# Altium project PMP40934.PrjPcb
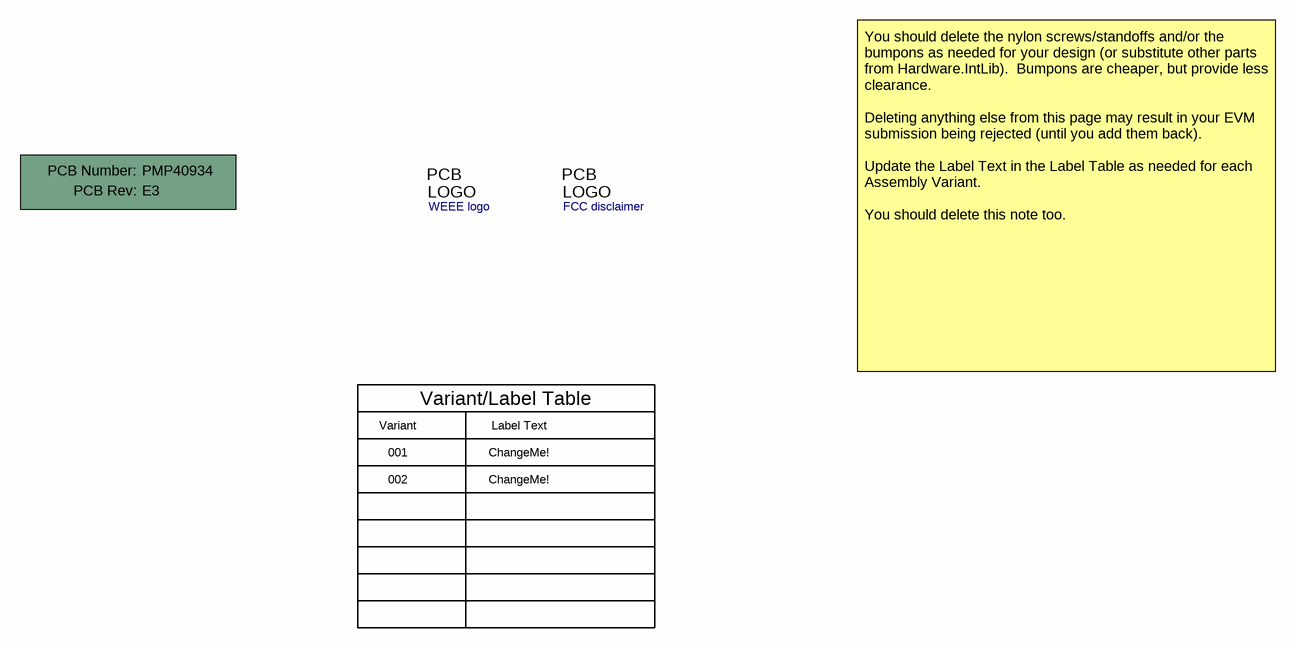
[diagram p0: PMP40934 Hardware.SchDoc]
TID: N/A; TechSupport: http://www.ti.com/support; SCH_Rev: E2; PRJ_Title: Change in menu Project|Project Options|Parameters; PRJ_Number: PMP40934; PRJ_Engineer: Enter name of project lead; PRJ_Customer: Public Release; PCB_Rev: E3; PCB_Layout: Who did the Layout?; CopyrightYear: 2020
3 sheets, 71 parts. Net scope: global (net labels, ports and power ports of the same name join across sheets).
Board file: PMP40934 PCB.PcbDoc
Sheets:
  PMP40934 Hardware.SchDoc
  PMP40934 Input filter.SchDoc
  PMP40934 TPS25762-Q1.SchDoc

## Sheet PMP40934 Hardware.SchDoc
size 431 x 279 mm; Date: Not shown in title block; ApprovedBy: Not shown in title block; CheckedBy: Not shown in title block; Author: Not shown in title block; CompanyName: Not shown in title block; Engineer: Not shown in title block; Organization: Not shown in title block; Address1: Not shown in title block; Address2: Not shown in title block; Address3: Not shown in title block; Address4: Not shown in title block; DocumentNumber: 3; Revision: Use project parameter SCH_Rev; SheetNumber: 3; SheetTotal: 3; PageSetup: Record=PageOptions¦CenterHorizontal=True¦CenterVertical=True¦PrintScale=1.00¦XCorrection=1.00¦YCorrection=1.00¦PrintKind=0¦BorderSize=5000000¦LeftOffset=0¦BottomOffset=0¦Orientation=2¦PaperLength=1000¦PaperWidth=1000¦Scale=100¦PaperSource=15¦PrintQuality=600¦MediaType=1¦DitherType=10¦PaperKind=Letter¦PrintScaleMode=1

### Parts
!PCB1  Printed Circuit Board  (value not drawn)  (mechanical)
Logo1  WEEE logo  [WEEE_Minimum]  (no BOM)
Logo3  FCC disclaimer  [FCC_disclaimer]  (no BOM)

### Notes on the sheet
- Variant
- Variant/Label Table
- Label Text
- You should delete the nylon screws/standoffs and/or the bumpons as needed for your design (or substitute other parts from Hardware.IntLib).  Bumpons are cheaper, but provide less clearance.
  Deleting anything else from this page may result in your EVM submission being rejected (until you add them back).
  Update the Label Text in the Label Table as needed for each Assembly Variant.
  You should delete this note too.
- 001
- 002
- ChangeMe!

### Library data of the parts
!PCB1 = CMP-0003618-2: Manufacturer: Any; PartNumber: PMP40934
Logo1 = CMP-0074769-1
Logo3 = CMP-0074847-1: FCC_disclaimer

## Sheet PMP40934 Input filter.SchDoc
size 431 x 279 mm; Date: Not shown in title block; ApprovedBy: Not shown in title block; CheckedBy: Not shown in title block; Author: Not shown in title block; CompanyName: Not shown in title block; Engineer: Not shown in title block; Organization: Not shown in title block; Address1: Not shown in title block; Address2: Not shown in title block; Address3: Not shown in title block; Address4: Not shown in title block; DocumentNumber: 2; Revision: Use project parameter SCH_Rev; SheetNumber: 2; SheetTotal: 3; PageSetup: Record=PageOptions¦CenterHorizontal=True¦CenterVertical=True¦PrintScale=1.00¦XCorrection=1.00¦YCorrection=1.00¦PrintKind=0¦BorderSize=5000000¦LeftOffset=0¦BottomOffset=0¦Orientation=2¦PaperLength=1000¦PaperWidth=1000¦Scale=100¦PaperSource=15¦PrintQuality=600¦MediaType=1¦DitherType=10¦PaperKind=Letter¦PrintScaleMode=1
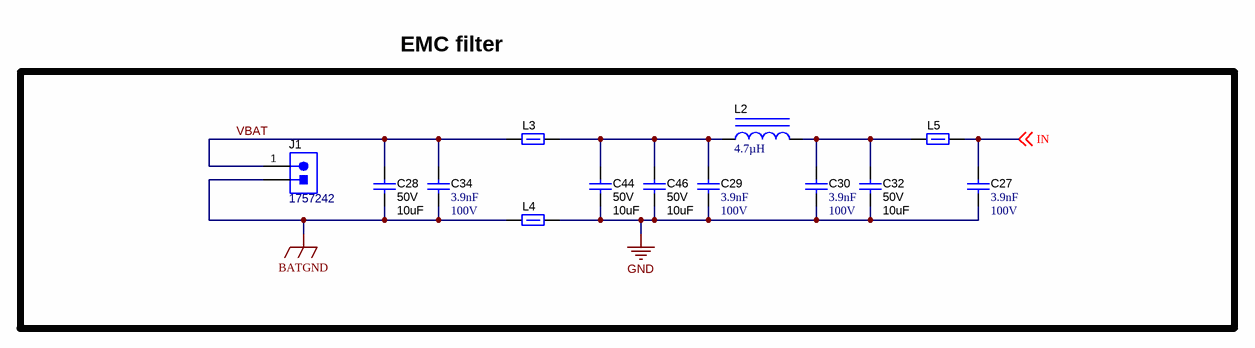
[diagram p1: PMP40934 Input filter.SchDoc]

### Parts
C27  Cap_F: 3.9nF  VDC_V: 100V  [0603]  (hidden comment: GCM1887U2A392JA16D)
C28  VDC_V: 50V  ValueDisplayed: 10uF  [1206_190]  (hidden comment: GRT31CD71H106KE13L)
C29  Cap_F: 3.9nF  VDC_V: 100V  [0603]  (hidden comment: GCM1887U2A392JA16D)
C30  Cap_F: 3.9nF  VDC_V: 100V  [0603]  (hidden comment: GCM1887U2A392JA16D)
C32  VDC_V: 50V  ValueDisplayed: 10uF  [1206_190]  (hidden comment: GRT31CD71H106KE13L)
C34  Cap_F: 3.9nF  VDC_V: 100V  [0603]  (hidden comment: GCM1887U2A392JA16D)
C44  VDC_V: 50V  ValueDisplayed: 10uF  [1206_190]  (hidden comment: GRT31CD71H106KE13L)
C46  VDC_V: 50V  ValueDisplayed: 10uF  [1206_190]  (hidden comment: GRT31CD71H106KE13L)
J1  1757242  [PHOENIX_1757242]
L2  ValueDisplayed: 4.7µH  [XFL5030]  (hidden comment: XFL5030-472MEC)
L3  BLM31SN500SZ1L  [1206]  (value not drawn)
L4  BLM31SN500SZ1L  [1206]  (value not drawn)
L5  BLM31SN500SZ1L  [1206]  (value not drawn)

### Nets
BATGND: C28.2 C34.2 J1.2 L4.1
GND: C27.2 C29.2 C30.2 C32.2 C44.2 C46.2 L4.2  [project net AGND]
IN: C27.1 L5.2 ; off-sheet IN
VBAT: C28.1 C34.1 J1.1 L3.1
NetC29_1: C29.1 C44.1 C46.1 L2.1 L3.2
NetC30_1: C30.1 C32.1 L2.2 L5.1

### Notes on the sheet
- EMC filter

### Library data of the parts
C27 C29 C30 C34 = CMP-0007481-1: CAP, CERM, 3900 pF, 100 V, +/- 10%, X7R, 0603; Manufacturer: MuRata; PartNumber: GRM188R72A392KA01D; TaMin_C: -55°C; Polarized: N; SizeAreaWB_mm2: 4.68; Value1: Unknown; U/M: EA; Value: 3900pF; TaMax_C: 125°C; SizeZ_mm: 1; SizeX_mm: 1.6; SizeY_mm: 0.8; SizeArea_mm2: 1.28; AEC Category: Q200
C28 C32 C44 C46 = CMP-0008808-1: CAP, CERM, 10 µF, 50 V,+/- 10%, X7R, AEC-Q200 Grade 1, 1206; Manufacturer: MuRata; TaMin_C: -55°C; Polarized: N; TempCo: X7T; SizeAreaWB_mm2: 10.92; Value1: Unknown; U/M: EA; Value: 10uF; TaMax_C: 125°C; SizeZ_mm: 1.9; SizeX_mm: 3.2; SizeY_mm: 1.6; Cap_Case: 1206; SizeArea_mm2: 5.12; Cap_F: 10µF; AEC Category: Q200
J1 = CMP-0055534-1: Header (Shrouded), 5.08 mm, 2x1, Tin, R/A, TH; Manufacturer: Phoenix Contact; CT: FALSE
L2 = CMP-0076756-1: Inductor, Shielded, Composite, 4.7 µH, 2.5 A, 0.022 ohm, AEC-Q200 Grade 1, SMD; Manufacturer: Coilcraft; SizeAreaWB_mm2: 54.4544; Irms: 8.7A @ 40C rise; SizeArea_mm2: 28.9344; AEC Qualified: Y; AEC Category: Q200; Value: 4.7uH; SizeZ_mm: 3.1; Imax_A: 2.5A; AEC Grade: 1; SizeY_mm: 5.28; Isat: 2.5A @ 10% inductance drop; DCR_ohm: 0.022; SizeX_mm: 5.48
L3-L5 = CMP-0003367-1: Ferrite Bead, 50 ohm @ 100 MHz, 12 A, 1206; Manufacturer: MuRata; ZTyp@100MHz_Ohm: 50; SizeAreaWB_mm2: 10.92; DCR_ohm: 1.6m; Value1: 0.0016 ohm; Value: 50 ohm; Imax_A: 12A; SizeZ_mm: 1.35; SizeX_mm: 3.2; SizeY_mm: 1.6; SizeArea_mm2: 5.12

## Sheet PMP40934 TPS25762-Q1.SchDoc
size 431 x 279 mm; Date: Not shown in title block; ApprovedBy: Not shown in title block; CheckedBy: Not shown in title block; Author: Not shown in title block; CompanyName: Not shown in title block; Engineer: Not shown in title block; Organization: Not shown in title block; Address1: Not shown in title block; Address2: Not shown in title block; Address3: Not shown in title block; Address4: Not shown in title block; DocumentNumber: 2; Revision: Use project parameter SCH_Rev; SheetNumber: 2; SheetTotal: 3; PageSetup: Record=PageOptions¦CenterHorizontal=True¦CenterVertical=True¦PrintScale=1.00¦XCorrection=1.00¦YCorrection=1.00¦PrintKind=0¦BorderSize=5000000¦LeftOffset=0¦BottomOffset=0¦Orientation=2¦PaperLength=1000¦PaperWidth=1000¦Scale=100¦PaperSource=15¦PrintQuality=600¦MediaType=1¦DitherType=10¦PaperKind=Letter¦PrintScaleMode=1
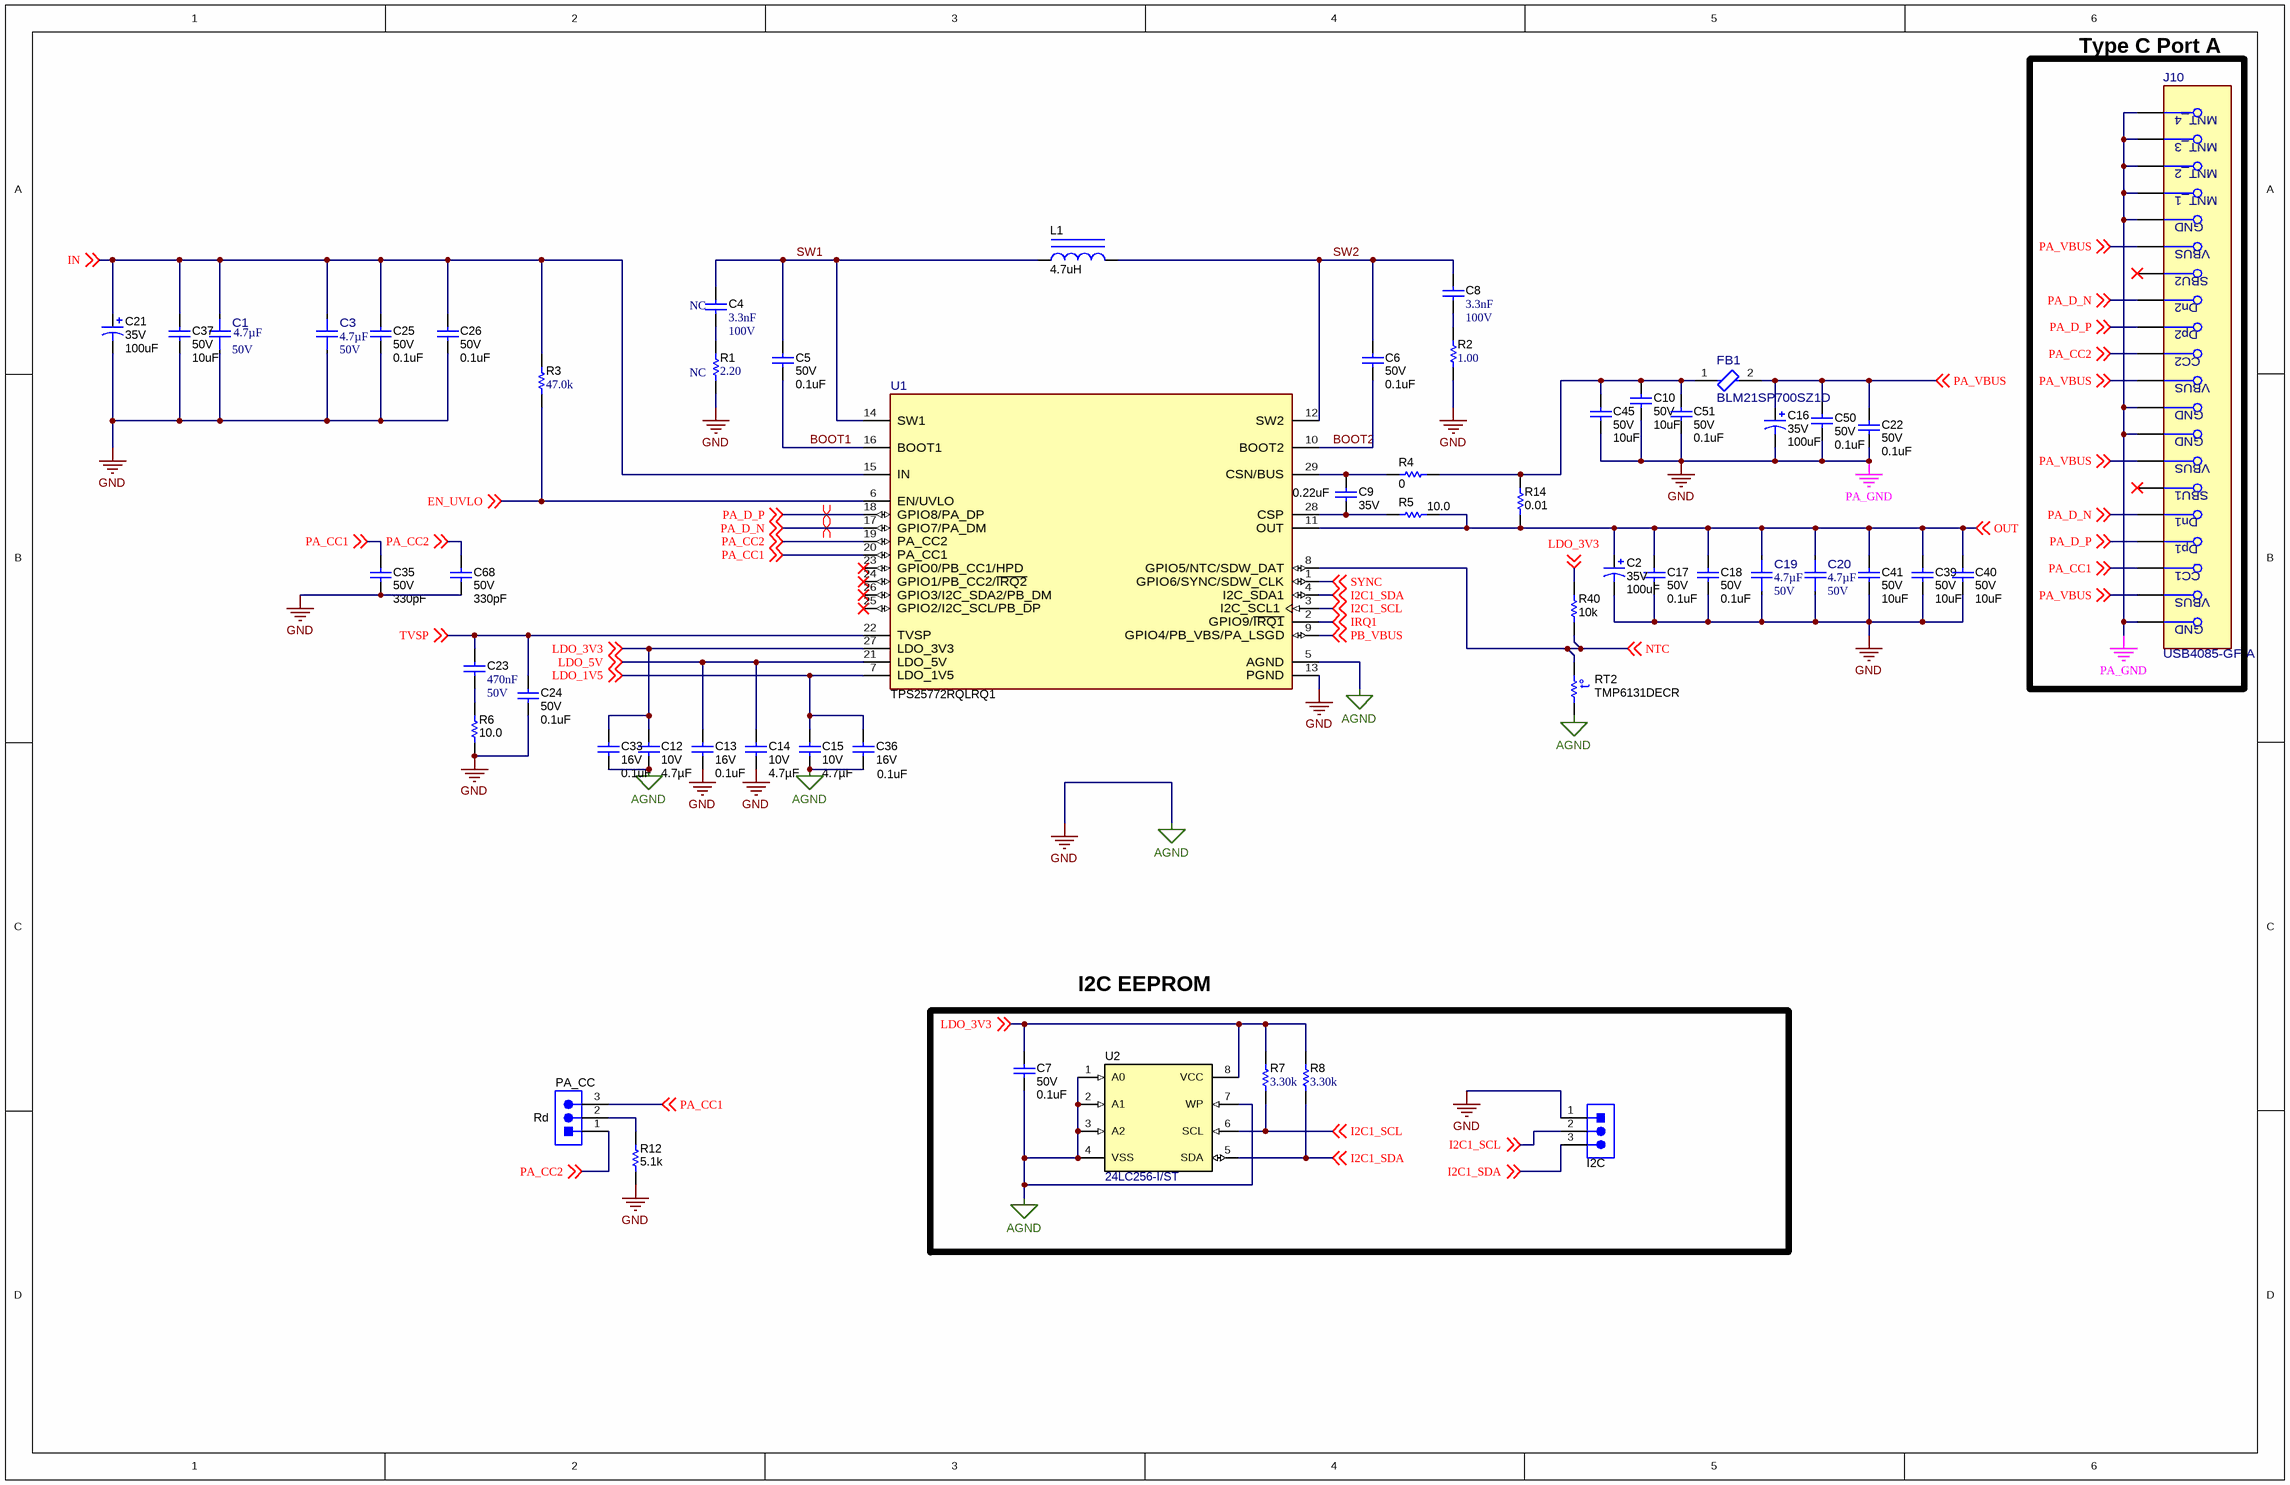
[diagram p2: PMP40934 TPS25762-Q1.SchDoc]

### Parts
C1  Cap_F: 4.7µF  VDC_V: 50V  [FP-CGA4J1X7R1H475K125AC_0805-MFG]  (hidden comment: GRT21BC71H475KE13L)
C2  VDC_V: 35V  ValueDisplayed: 100uF  [Panasonic_D]  (hidden comment: EEHZK1V101XP)
C3  Cap_F: 4.7µF  VDC_V: 50V  [FP-CGA4J1X7R1H475K125AC_0805-MFG]  (hidden comment: GRT21BC71H475KE13L)
C4  Cap_F: 3.3nF  VDC_V: 100V  [0603]  (hidden comment: GRM188R72A332KA01D)
C5  VDC_V: 50V  ValueDisplayed: 0.1uF  [0402L]  (hidden comment: GRT155R71H104KE01D)
C6  VDC_V: 50V  ValueDisplayed: 0.1uF  [0402L]  (hidden comment: GRT155R71H104KE01D)
C7  VDC_V: 50V  ValueDisplayed: 0.1uF  [0402L]  (hidden comment: GRT155R71H104KE01D)
C8  Cap_F: 3.3nF  VDC_V: 100V  [0603]  (hidden comment: GRM188R72A332KA01D)
C9  VDC_V: 35V  ValueDisplayed: 0.22uF  [0402L]  (hidden comment: CGA3E2X7R1H104K080AA)
C10  VDC_V: 50V  ValueDisplayed: 10uF  [1206_190]  (hidden comment: GRT31CD71H106KE13L)
C12  VDC_V: 10V  Cap_F: 4.7µF  [0805L]  (hidden comment: GCM21BR71C475KA73K)
C13  VDC_V: 16V  ValueDisplayed: 0.1uF  [0402L]  (hidden comment: GRT155R71H104KE01D)
C14  VDC_V: 10V  Cap_F: 4.7µF  [0805L]  (hidden comment: GCM21BR71C475KA73K)
C15  VDC_V: 10V  Cap_F: 4.7µF  [0805L]  (hidden comment: GCM21BR71C475KA73K)
C16  VDC_V: 35V  ValueDisplayed: 100uF  [Panasonic_D]  (hidden comment: EEHZK1V101XP)
C17  VDC_V: 50V  ValueDisplayed: 0.1uF  [0402L]  (hidden comment: GRT155R71H104KE01D)
C18  VDC_V: 50V  ValueDisplayed: 0.1uF  [0402L]  (hidden comment: GRT155R71H104KE01D)
C19  Cap_F: 4.7µF  VDC_V: 50V  [FP-CGA4J1X7R1H475K125AC_0805-MFG]  (hidden comment: GRT21BC71H475KE13L)
C20  Cap_F: 4.7µF  VDC_V: 50V  [FP-CGA4J1X7R1H475K125AC_0805-MFG]  (hidden comment: GRT21BC71H475KE13L)
C21  VDC_V: 35V  ValueDisplayed: 100uF  [Panasonic_D]  (hidden comment: EEHZK1V101XP)
C22  VDC_V: 50V  ValueDisplayed: 0.1uF  [0402L]  (hidden comment: GRT155R71H104KE01D)
C23  Cap_F: 470nF  VDC_V: 50V  [0603]  (hidden comment: CGA3E3X7R1H474K080AE)
C24  VDC_V: 50V  ValueDisplayed: 0.1uF  [0402L]  (hidden comment: GRT155R71H104KE01D)
C25  VDC_V: 50V  ValueDisplayed: 0.1uF  [0402L]  (hidden comment: GRT155R71H104KE01D)
C26  VDC_V: 50V  ValueDisplayed: 0.1uF  [0402L]  (hidden comment: GRT155R71H104KE01D)
C33  VDC_V: 16V  ValueDisplayed: 0.1uF  [0402L]  (hidden comment: GRT155R71H104KE01D)
C35  VDC_V: 50V  ValueDisplayed: 330pF  [0402]  (hidden comment: GRM155R71H331KA01D)
C36  VDC_V: 16V  ValueDisplayed: 0.1uF  [0402L]  (hidden comment: GRT155R71H104KE01D)
C37  VDC_V: 50V  ValueDisplayed: 10uF  [1206_190]  (hidden comment: GRT31CD71H106KE13L)
C39  VDC_V: 50V  ValueDisplayed: 10uF  [1206_190]  (hidden comment: GRT31CD71H106KE13L)
C40  VDC_V: 50V  ValueDisplayed: 10uF  [1206_190]  (hidden comment: GRT31CD71H106KE13L)
C41  VDC_V: 50V  ValueDisplayed: 10uF  [1206_190]  (hidden comment: GRT31CD71H106KE13L)
C45  VDC_V: 50V  ValueDisplayed: 10uF  [1206_190]  (hidden comment: GRT31CD71H106KE13L)
C50  VDC_V: 50V  ValueDisplayed: 0.1uF  [0402L]  (hidden comment: GRT155R71H104KE01D)
C51  VDC_V: 50V  ValueDisplayed: 0.1uF  [0402L]  (hidden comment: GRT155R71H104KE01D)
C68  VDC_V: 50V  ValueDisplayed: 330pF  [0402]  (hidden comment: GRM155R71H331KA01D)
FB1  BLM21SP700SZ1D  [0805_HV1]
I2C  61300311121  [WURTH_61300311121]  (value not drawn)
J10  USB4085-GF-A  [FP-USB4085-GF-A_PTH_USB-C-MFG]
L1  ValueDisplayed: 4.7uH  [XAL1010]  (hidden comment: XAL1010-472MEB)
PA_CC  61300311121  [WURTH_61300311121]  (value not drawn)
R1  ValueDisplayed: 2.20  [1206]  (hidden comment: ERJ-8RQF2R2V)
R2  ValueDisplayed: 1.00  [1206]  (hidden comment: CRCW12061R00FKEA)
R3  ValueDisplayed: 47.0k  [0603]  (hidden comment: CRCW060347K0FKEA)
R4  ValueDisplayed: 0  [0402L]  (hidden comment: RMCF0603ZT0R00)
R5  ValueDisplayed: 10.0  [0402L]  (hidden comment: RMCF0603ZT0R00)
R6  ValueDisplayed: 10.0  [1206L]  (hidden comment: RC1206FR-0710RL)
R7  ValueDisplayed: 3.30k  [0402]  (hidden comment: RK73H1ETTP3301F)
R8  ValueDisplayed: 3.30k  [0402]  (hidden comment: RK73H1ETTP3301F)
R12  ValueDisplayed: 5.1k  [0603]  (hidden comment: CRCW06035K10JNEA)
R14  ValueDisplayed: 0.01  [2010]  (hidden comment: WSL2010R0100FEA18)
R40  ValueDisplayed: 10k  [0402L]  (hidden comment: ERJ-2GEJ103X)
RT2  TMP6131DECR  [DEC0002A]
U1  TPS25772RQLRQ1  [RQL0029A-MFG]
U2  24LC256-I/ST  [TSSOP-8]

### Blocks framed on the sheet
Type C Port A: J10

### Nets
AGND: C1.1 C2.2(-) C3.1 C7.1 C10.2 C12.2 C13.2 C14.2 C15.2 C16.2(-) C17.1 C18.1 C19.1 C20.1 C21.2(-) C22.1 C24.2 C25.1 C26.1 C33.2 C35.2 C36.2 C37.2 C39.2 C40.2 C41.2 C45.2 C50.1 C51.1 C68.2 I2C.1 J10.1(MNT_1) J10.2(MNT_2) J10.3(MNT_3) J10.4(MNT_4) J10.A1(GND) J10.A12(GND) J10.B1(GND) J10.B12(GND) R1.1 R2.1 R6.1 R12.1 RT2.1 U1.5(AGND) U1.13(PGND) U2.1(A0) U2.2(A1) U2.3(A2) U2.4(VSS) U2.7(WP)  [also labelled GND, PA_GND]
BOOT1: C5.1 U1.16(BOOT1)
BOOT2: C6.1 U1.10(BOOT2)
EN_UVLO: R3.1 U1.6(EN/UVLO) ; off-sheet EN_UVLO
I2C1_SCL: I2C.2 R7.1 U1.3(I2C_SCL1) U2.6(SCL) ; off-sheet I2C1_SCL
I2C1_SDA: I2C.3 R8.1 U1.4(I2C_SDA1) U2.5(SDA) ; off-sheet I2C1_SDA
IN: C1.2 C3.2 C21.1(+) C25.2 C26.2 C37.1 R3.2 U1.15(IN) ; off-sheet IN
IRQ1: U1.2(GPIO9/~{IRQ1}) ; off-sheet IRQ1
LDO_1V5: C15.1 C36.1 U1.7(LDO_1V5) ; off-sheet LDO_1V5
LDO_3V3: C7.2 C12.1 C33.1 R7.2 R8.2 R40.2 U1.27(LDO_3V3) U2.8(VCC) ; off-sheet LDO_3V3
LDO_5V: C13.1 C14.1 U1.21(LDO_5V) ; off-sheet LDO_5V
NTC: R40.1 RT2.2 U1.8(GPIO5/NTC/SDW_DAT) ; off-sheet NTC
OUT: C2.1(+) C17.2 C18.2 C19.2 C20.2 C39.1 C40.1 C41.1 R5.2 R14.2 U1.11(OUT) ; off-sheet OUT
PA_CC1: C35.1 J10.A5(CC1) PA_CC.3 U1.20(PA_CC1) ; off-sheet PA_CC1
PA_CC2: C68.1 J10.B5(CC2) PA_CC.1 U1.19(PA_CC2) ; off-sheet PA_CC2
PA_D_N: J10.A7(Dn1) J10.B7(Dn2) U1.17(GPIO7/PA_DM) ; off-sheet PA_D_N
PA_D_P: J10.A6(Dp1) J10.B6(Dp2) U1.18(GPIO8/PA_DP) ; off-sheet PA_D_P
PA_VBUS: C16.1(+) C22.2 C50.2 FB1.2 J10.A4(VBUS) J10.A9(VBUS) J10.B4(VBUS) J10.B9(VBUS) ; off-sheet PA_VBUS
PB_VBUS: U1.9(GPIO4/PB_VBS/PA_LSGD) ; off-sheet PB_VBUS
SW1: C4.1 C5.2 L1.1 U1.14(SW1)
SW2: C6.2 C8.1 L1.2 U1.12(SW2)
SYNC: U1.1(GPIO6/SYNC/SDW_CLK) ; off-sheet SYNC
TVSP: C23.1 C24.1 U1.22(TVSP) ; off-sheet TVSP
NetC4_2: C4.2 R1.2
NetC8_2: C8.2 R2.2
NetC9_1: C9.1 R5.1 U1.28(CSP)
NetC9_2: C9.2 R4.1 U1.29(CSN/BUS)
NetC10_1: C10.1 C45.1 C51.2 FB1.1 R4.2 R14.1
NetC23_2: C23.2 R6.2
NetPA_CC_2: PA_CC.2 R12.2

Not connected (* = marked no-connect by the designer): J10 A8(SBU1)* B8(SBU2)*; U1 23(GPIO0/PB_CC1/HPD)* 24(GPIO1/PB_CC2/~{IRQ2})* 25(GPIO2/I2C_SCL/PB_DP)* 26(GPIO3/I2C_SDA2/PB_DM)*

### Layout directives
differential pair: PA_D_N, PA_D_P

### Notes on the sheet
- (near C4) NC
- (near R1) NC
- I2C EEPROM
- (near PA_CC) Rd

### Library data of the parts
C1 = CMP-0090082-1: Cap Ceramic 4.7uF 50V X7R 10% Pad SMD 0805 +125°C Automotive T/R; Manufacturer: TDK Corporation; SizeZ_mm: 1.45mm; Tolerance_%: 0.1%; AEC Qualified: Yes; TempCo: 15%; AEC Grade: Grade 1; Value: 4.7µF
C2 C16 C21 = CMP-0010737-1: CAP, AL, 100 uF, 35 V, +/- 20%, 0.26 ohm, AEC-Q200 Grade 2, SMD; PartNumber: EEE-FT1V101AP; Manufacturer: Panasonic; CompType: Capacitor; Value: 100uF; ESR_ohm: 0.26; Polarized: Y; Cap_F: 100µF; TaMin_C: -55°C; TaMax_C: 105°C; Cap_Case: 6.3x5.8mm; AEC Category: Q200; AEC Grade: 2; SizeArea_mm2: 43.56; SizeAreaWB_mm2: 73.96; SizeX_mm: 6.6; SizeZ_mm: 6.1; U/M: EA
C3 C19 C20 = CMP-0090082-1: Cap Ceramic 4.7uF 50V X7R 10% Pad SMD 0805 +125°C Automotive T/R; PartNumber: CGA4J1X7R1H475K125AC; Manufacturer: TDK Corporation; SizeZ_mm: 1.45mm; Tolerance_%: 0.1%; AEC Qualified: Yes; TempCo: 15%; AEC Grade: Grade 1; Value: 4.7µF
C4 C8 = CMP-0007479-3: CAP, CERM, 3300 pF, 100 V, +/- 10%, X7R, 0603; Manufacturer: MuRata; TaMin_C: -55°C; Polarized: N; SizeAreaWB_mm2: 4.68; Value1: Unknown; U/M: EA; Value: 3300pF; TaMax_C: 125°C; SizeZ_mm: 1; SizeX_mm: 1.6; SizeY_mm: 0.8; SizeArea_mm2: 1.28; AEC Category: Q200
C5-C7 = CMP-0006325-2: CAP, CERM, 0.1 uF, 50 V, +/- 10%, X7R, AEC-Q200 Grade 1, 0402; Manufacturer: TDK; PartNumber: CGA2B3X7R1H104K050BB; TaMin_C: -55°C; ESR_ohm: 0.039064; Polarized: N; SizeAreaWB_mm2: 3; Value1: 0.039064 ohm; U/M: EA; Value: 0.1uF; TaMax_C: 125°C; SizeZ_mm: 0.6; SizeX_mm: 1; SizeY_mm: 0.5; Cap_Case: 0402; AEC Qualified: Y; Cap_F: 100nF; IRMS_A: 814.669mA; AEC Category: Q200
C9 = CMP-0006325-2: CAP, CERM, 0.22 uF, 35 V, +/- 10%, X7R, AEC-Q200 Grade 1, 0402; Manufacturer: TDK; PartNumber: CGA2B1X7R1V224K050BC; TaMin_C: -55°C; ESR_ohm: 0.039064; Polarized: N; SizeAreaWB_mm2: 3; Value1: 0.039064 ohm; U/M: EA; Value: 0.22uF; TaMax_C: 125°C; SizeZ_mm: 0.6; SizeX_mm: 1; SizeY_mm: 0.5; Cap_Case: 0402; Value2: 50V; AEC Qualified: Y; Cap_F: 220nF; IRMS_A: 814.669mA; AEC Category: Q200
C10 C37 C39-C41 C45 = CMP-0008808-1: as C28 on sheet PMP40934 Input filter
C12 C14 C15 = CMP-0084739-1: CAP, CERM, 4.7 µF, 10 V,+/- 10%, X7R, AEC-Q200 Grade 1, 0805; PartNumber: CGA4J1X7R1H475K125AC; Manufacturer: TDK; SizeZ_mm: 1.45; AEC Qualified: Y; Cap_Case: 0805; Polarized: N; SizeAreaWB_mm2: 6.75; TaMax_C: 125°C; Value: 4.7uF; AEC Category: Q200; SizeArea_mm2: 2.5; TaMin_C: -55°C; U/M: EA; AEC Grade: 1; SizeX_mm: 2; SizeY_mm: 1.25
C13 C33 C36 = CMP-0006201-2: CAP, CERM, 0.1 uF, 16 V, +/- 10%, X7R, 0402; Manufacturer: AVX; PartNumber: 0402YC104KAT2A; TaMin_C: -55°C; Polarized: N; SizeAreaWB_mm2: 3; Value1: Unknown; U/M: EA; Value: 0.1uF; TaMax_C: 125°C; SizeZ_mm: 0.6; SizeX_mm: 1; SizeY_mm: 0.5; Cap_Case: 0402; Cap_F: 100nF; AEC Category: Q200
C17 C18 C22 C24-C26 C50 C51 = CMP-0006325-2: CAP, CERM, 0.1 uF, 50 V, +/- 10%, X7R, AEC-Q200 Grade 1, 0402; Manufacturer: Murata; TaMin_C: -55°C; ESR_ohm: 0.039064; Polarized: N; SizeAreaWB_mm2: 3; Value1: 0.039064 ohm; U/M: EA; Value: 0.1uF; TaMax_C: 125°C; SizeZ_mm: 0.6; SizeX_mm: 1; SizeY_mm: 0.5; Cap_Case: 0402; AEC Qualified: Y; Cap_F: 100nF; IRMS_A: 814.669mA; AEC Category: Q200
C23 = CMP-0007097-2: CAP, CERM, 0.47 uF, 50 V, +/- 10%, X7R, AEC-Q200 Grade 1, 0603; Manufacturer: TDK; TaMin_C: -55°C; Polarized: N; SizeAreaWB_mm2: 4.68; Value1: Unknown; U/M: EA; Value: 0.47uF; TaMax_C: 125°C; SizeZ_mm: 1; SizeX_mm: 1.6; SizeY_mm: 0.8; SizeArea_mm2: 1.28; AEC Qualified: Y; AEC Category: Q200
C35 C68 = CMP-0006687-2: CAP, CERM, 330 pF, 50 V, +/- 10%, X7R, 0402; Manufacturer: MuRata; TaMin_C: -55°C; Polarized: N; SizeAreaWB_mm2: 3; Value1: Unknown; U/M: EA; Value: 330pF; TaMax_C: 125°C; SizeZ_mm: 0.6; SizeX_mm: 1; SizeY_mm: 0.5; AEC Category: Q200
FB1 = CMP-0091807-2: Chip Ferrite Bead, 0805, 110Ω @ 100MHz, 0.013Ω, 25%, 5A; Manufacturer: Murata; Part Number: BLM21SP111BH1D; AEC Qualified: Yes; DCR_ohm: 0.013; SizeZ_mm: 1.05mm; Ciiva Ids: 886678; Tolerance_%: 0.25%; AEC Grade: Grade 0; Import Ts: 1521843479
I2C PA_CC = CMP-0054796-1: Header, 2.54 mm, 3x1, Gold, TH; Manufacturer: Wurth Elektronik; CNHeader: TRUE; Green_Lifecycle: Active; Green_REACh: Passed; CT: FALSE
J10 = CMP-0087858-1: USB - C (Type - C) USB 2.0 Receptacle Connector 16 Position Through Hole, Right Angle; Manufacturer: Global Connector Technology; Current_A: 4.25A; Voltage_V: 20V; ContactFinish: Gold,Nickel; Shrouded: true
L1 = CMP-0060950-1: Inductor, Shielded, Composite, 4.7 uH, 24 A, 0.01 ohm, SMD; Manufacturer: Coilcraft; Isat: 25.4A @ 30% inductance drop; Green_Lifecycle: Not Set; SizeAreaWB_mm2: 159.6; DCR_ohm: 0.01; Green_REACh: Incomplete; Irms: 24A @ 40C rise; Value: 4.7uH; Imax_A: 24A; SizeZ_mm: 10; SizeX_mm: 11.3; SizeArea_mm2: 113; Ind_H: 4.7µH; AEC Category: Q200
R1 = CMP-0017777-3: RES, 2.20, 1%, 0.25 W, AEC-Q200 Grade 0, 1206; Manufacturer: Panasonic; Power_W: 250mW; TempCo: 200 ppm/C; Value_Code: 2R20; Value: 2.20; Res_ohm: 2.2; SizeX_mm: 3.2; SizeY_mm: 1.6; SizeZ_mm: 1.35; Value2: 0.25W; SizeArea_mm2: 5.12; AEC Qualified: Y; AEC Category: Q200; AEC Grade: 0; SizeAreaWB_mm2: 10.92
R2 = CMP-0016745-3: RES, 1.00, 1%, 0.25 W, AEC-Q200 Grade 0, 1206; Manufacturer: Vishay-Dale; Power_W: 250mW; TempCo: 100 ppm/C; Value_Code: 1R00; Value: 1.00; EIA_Code: E96; Res_ohm: 1; SizeX_mm: 3.2; SizeY_mm: 1.6; SizeZ_mm: 1.35; Value2: 0.25W; SizeArea_mm2: 5.12; AEC Qualified: Y; VDC_V: 200V; AEC Category: Q200; AEC Grade: 0
R3 = CMP-0022438-1: RES, 47.0 k, 1%, 0.1 W, AEC-Q200 Grade 0, 0603; Manufacturer: Vishay-Dale; Power_W: 100mW; TempCo: 100 ppm/C; Value_Code: 47k0; U/M: EA; Value: 47.0k; Res_ohm: 47k; SizeX_mm: 1.6; SizeY_mm: 0.8; SizeZ_mm: 1; Value2: 0.1W; SizeArea_mm2: 1.28; AEC Qualified: Y; VDC_V: 75V; AEC Grade: 0; AEC Category: Q200
R4 = CMP-0081856-1: RES, 0, 0%, 0.2 W, AEC-Q200 Grade 0, 0402; PartNumber: CRCW04020000Z0EDHP; Manufacturer: Vishay-Dale; SizeAreaWB_mm2: 3; SizeArea_mm2: 0.5; AEC Qualified: Y; AEC Category: Q200; Value: 0; SizeZ_mm: 0.6; Power_W: 200mW; VDC_V: 50V; Value2: 0.2W; SizeX_mm: 1
R5 = CMP-0025963-2: RES, 10.0, 1%, 0.063 W, 0402; Manufacturer: Vishay-Dale; PartNumber: CRCW040210R0FKED; Power_W: 63mW; TempCo: 100 ppm/C; Value_Code: 10R0; U/M: EA; Value: 10.0; EIA_Code: E96; Res_ohm: 10; SizeX_mm: 1; SizeY_mm: 0.5; SizeZ_mm: 0.6; Value2: 0.063W; VDC_V: 50V; AEC Category: Q200
R6 = CMP-0017851-1: RES, 10.0, 1%, 0.25 W, 1206; Manufacturer: Yageo America; Power_W: 250mW; TempCo: 200 ppm/C; Value_Code: 10R0; U/M: EA; Value: 10.0; EIA_Code: E96; Res_ohm: 10; SizeX_mm: 3.2; SizeY_mm: 1.6; SizeZ_mm: 1.35; Value2: 0.25W; SizeArea_mm2: 5.12; VDC_V: 200V; AEC Category: Q200
R7 R8 = CMP-0026750-1: RES, 3.30 k, 1%, 0.063 W, AEC-Q200 Grade 0, 0402; Manufacturer: KOA Speer; Power_W: 63mW; TempCo: 100 ppm/C; Value_Code: 3k30; U/M: EA; Value: 3.30k; Res_ohm: 3.3k; SizeX_mm: 1; SizeY_mm: 0.5; SizeZ_mm: 0.6; Value2: 0.063W; AEC Qualified: Y; VDC_V: 50V; AEC Grade: 0; AEC Category: Q200
R12 = CMP-0025830-4: RES, 5.1 k, 5%, 0.1 W, AEC-Q200 Grade 0, 0603; Manufacturer: Vishay-Dale; Power_W: 100mW; TempCo: 200 ppm/C; Value_Code: 5k10; Value: 5.1k; EIA_Code: E24; SizeX_mm: 1.6; SizeY_mm: 0.8; SizeZ_mm: 1; Value2: 0.1W; SizeArea_mm2: 1.28; CompType: Resistor; AEC Qualified: Y; VDC_V: 75V; AEC Category: Q200; AEC Grade: 0
R14 = CMP-0016557-2: RES, 0.01, 1%, 1 W, 2010; Manufacturer: Vishay-Dale; Power_W: 1W; TempCo: 75 ppm/C; Value_Code: R010; U/M: EA; Value: 0.01; EIA_Code: E96; SizeX_mm: 5; SizeY_mm: 2.5; SizeZ_mm: 1.66; SizeArea_mm2: 12.5; AEC Category: Q200
R40 = CMP-0026994-4: RES, 10 k, 5%, 0.1 W, AEC-Q200 Grade 0, 0402; Manufacturer: Panasonic; Power_W: 100mW; TempCo: 200 ppm/C; Value_Code: 10k0; U/M: EA; Value: 10k; EIA_Code: E24; SizeX_mm: 1; SizeY_mm: 0.5; SizeZ_mm: 0.6; Value2: 0.1W; AEC Qualified: Y; VDC_V: 50V; AEC Grade: 0; AEC Category: Q200
RT2 = CMP-0084566-1: Thermistor, DEC0002A (X1SON-2); Alternate Manufacturer: Texas Instruments; Alternate PartNumber: TMP6131DECT; CompType: IC; AEC Category: Q200; SizeX_mm: 1; AEC Qualified: N; SizeZ_mm: 0.5; SizeArea_mm2: 0.6; SizeAreaWB_mm2: 3.2
U1 = CMP-0088771-1: Automotive Dual USB Type-C Power Delivery Controller with Buck-Boost Regulator; Manufacturer: Texas Instruments; Nominal Supply Current: 2-60mA; TaMax_C: +125°C; Output Voltage: 3-21V; AEC Qualified: Yes; Number Of Outputs: 1; TJmax_C: +150°C; Standoff Height: 0mm; AEC Grade: Grade 1; Output Type: AdjustableProgrammable; TaMin_C: -40°C; Min Supply Voltage: 4.5V; Max Supply Voltage: 18V; SizeZ_mm: 1mm; Switching Frequency: 300/400/450kHz
U2 = CMP-0005262-2: 256K I2C CMOS Serial EEPROM, TSSOP-8; Manufacturer: Microchip; SizeAreaWB_mm2: 42; SizeZ_mm: 1.2; SizeX_mm: 6.4; SizeY_mm: 3; SizeArea_mm2: 19.2

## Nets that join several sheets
AGND: PMP40934 Input filter (7 pins), PMP40934 TPS25762-Q1 (51 pins)
IN: PMP40934 Input filter (C27.1 L5.2), PMP40934 TPS25762-Q1 (8 pins)

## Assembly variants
001: not fitted FID1 FID2 FID3 L5 L6 L7 L8
EMC_FERRITE_BEAD: not fitted R43 RT1
PTC: all parts fitted
JTAG Enabled: all parts fitted
HUB: all parts fitted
